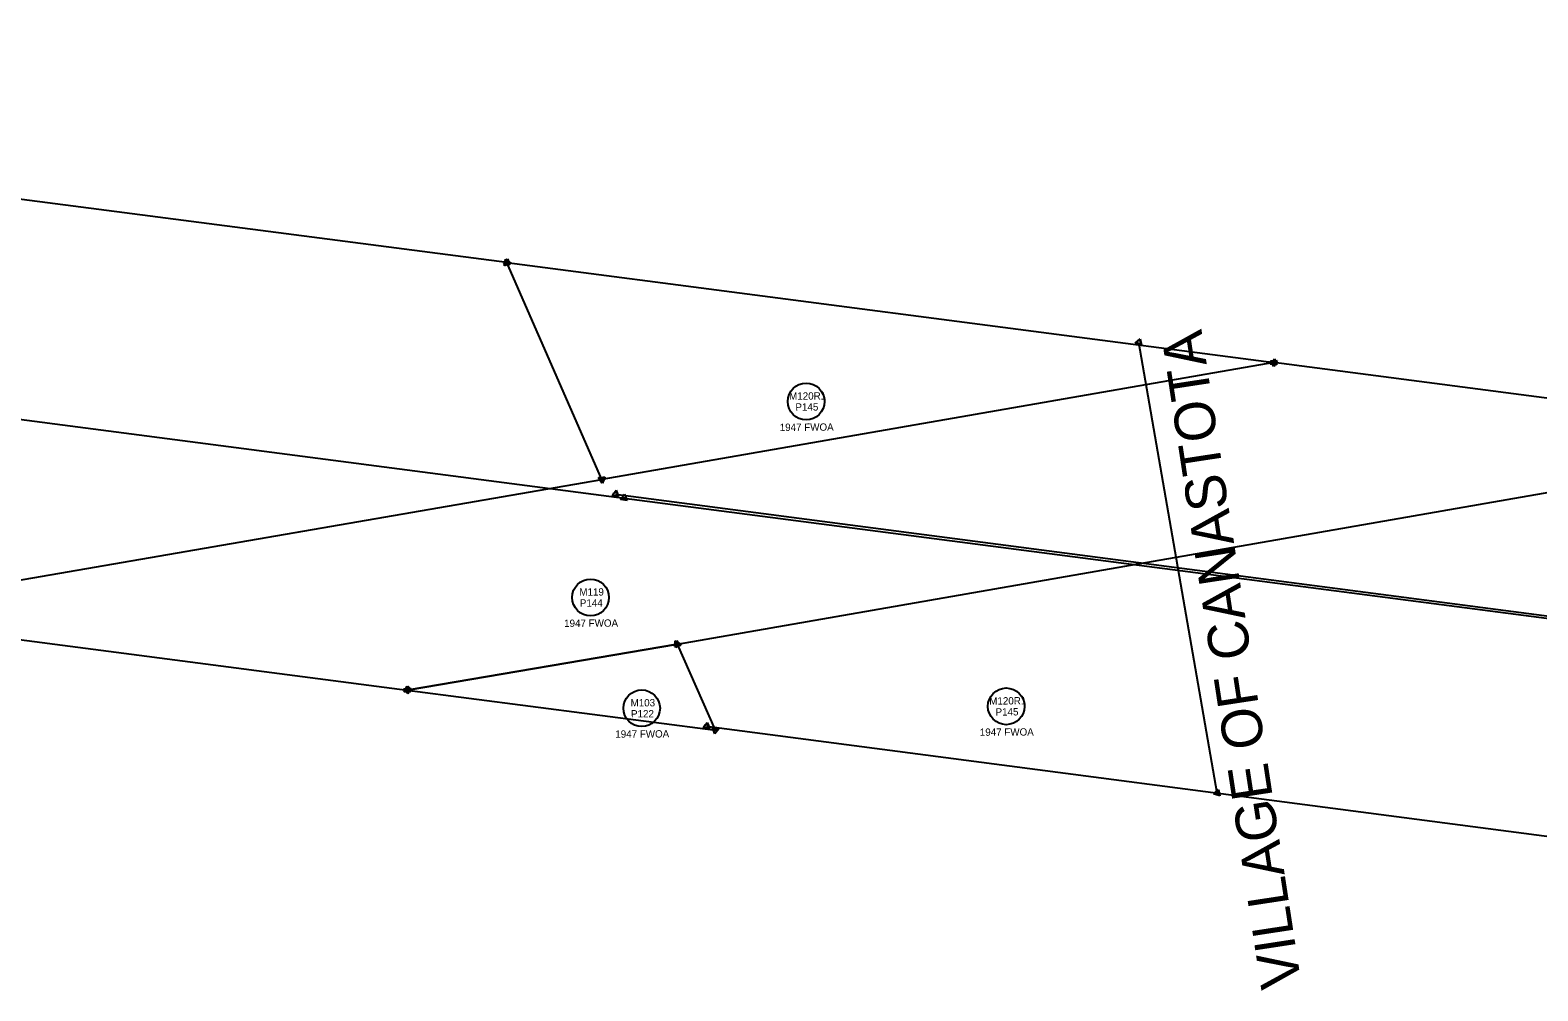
# Model space of a CAD drawing. Extents: x 981880 to 1042422, y 1126107 to 1131189.
# Drawn here: x 1036181 to 1037044, y 1127019 to 1127569 of the extents above; entities that cross this region are included whole.
import ezdxf

# ---------------------------------------------------------------- set-up
doc = ezdxf.new("R2010")
doc.units = 0
for name, color, linetype in [('ADEFAULT', 7, 'Continuous'), ('Level 56', 7, 'Continuous'), ('MHBWOA', 7, 'Continuous'), ('MJV', 7, 'Continuous'), ('MJV_C', 7, 'Continuous'), ('MRBL2', 7, 'Continuous'), ('MRBL3', 7, 'Continuous')]:
    doc.layers.add(name, color=color, linetype=linetype)

msp = doc.modelspace()

# ---------------------------------------------------------------- linework, layer by layer
at = {"layer": 'ADEFAULT'}
for points in [[(1036451.89, 1127435.41), (1036454.19, 1127438.41)], [(1036452.6, 1127434.51), (1036453.05, 1127438.26)], [(1036456.07, 1127435.99), (1036452.6, 1127434.51)], [(1036453.05, 1127438.26), (1036456.07, 1127435.99)], [(1036454.19, 1127438.41), (1036455.64, 1127434.92)], [(1036455.64, 1127434.92), (1036451.89, 1127435.41)], [(1036813.77, 1127390.21), (1036816.67, 1127392.64)], [(1036816.67, 1127392.64), (1036817.32, 1127388.91)], [(1036817.32, 1127388.91), (1036813.77, 1127390.21)], [(1036891.18, 1127378.19), (1036893.48, 1127381.19)], [(1036894.93, 1127377.7), (1036891.18, 1127378.19)], [(1036891.28, 1127380.08), (1036895.06, 1127380.17)], [(1036893.24, 1127376.85), (1036891.28, 1127380.08)], [(1036895.06, 1127380.17), (1036893.24, 1127376.85)], [(1036893.48, 1127381.19), (1036894.93, 1127377.7)], [(1036506.29, 1127312.94), (1036510.01, 1127313.58)], [(1036508.71, 1127310.04), (1036506.29, 1127312.94)], [(1036506.42, 1127313.21), (1036510.19, 1127313.33)], [(1036508.4, 1127310), (1036506.42, 1127313.21)], [(1036510.19, 1127313.33), (1036508.4, 1127310)], [(1036510.01, 1127313.58), (1036508.71, 1127310.04)], [(1036514.1, 1127302.92), (1036516.4, 1127305.92)], [(1036517.85, 1127302.43), (1036514.1, 1127302.92)], [(1036516.4, 1127305.92), (1036517.85, 1127302.43)], [(1036519.04, 1127300.61), (1036521.34, 1127303.61)], [(1036522.79, 1127300.12), (1036519.04, 1127300.61)], [(1036521.34, 1127303.61), (1036522.79, 1127300.12)], [(1036549.83, 1127216.42), (1036551.14, 1127219.96)], [(1036551.14, 1127219.96), (1036553.56, 1127217.06)], [(1036553.56, 1127217.06), (1036549.83, 1127216.42)], [(1036550.48, 1127215.9), (1036550.36, 1127219.67)], [(1036550.36, 1127219.67), (1036553.69, 1127217.88)], [(1036553.69, 1127217.88), (1036550.48, 1127215.9)], [(1036394.78, 1127192.34), (1036398.5, 1127192.97)], [(1036397.19, 1127189.43), (1036394.78, 1127192.34)], [(1036394.81, 1127190.73), (1036397.1, 1127193.73)], [(1036398.56, 1127190.25), (1036394.81, 1127190.73)], [(1036394.96, 1127190.44), (1036396.78, 1127193.75)], [(1036398.73, 1127190.52), (1036394.96, 1127190.44)], [(1036396.78, 1127193.75), (1036398.73, 1127190.52)], [(1036397.1, 1127193.73), (1036398.56, 1127190.25)], [(1036398.5, 1127192.97), (1036397.19, 1127189.43)], [(1036566.3, 1127170.02), (1036568.59, 1127173.02)], [(1036570.04, 1127169.53), (1036566.3, 1127170.02)], [(1036568.59, 1127173.02), (1036570.04, 1127169.53)], [(1036573.08, 1127166.41), (1036571.59, 1127169.89)], [(1036571.59, 1127169.89), (1036575.34, 1127169.44)], [(1036575.34, 1127169.44), (1036573.08, 1127166.41)], [(1036858.67, 1127132.21), (1036861.57, 1127134.63)], [(1036861.57, 1127134.63), (1036862.22, 1127130.9)], [(1036862.22, 1127130.9), (1036858.67, 1127132.21)]]:
    msp.add_lwpolyline(points, dxfattribs=at)
for centre, radius in [((1036453.91, 1127436.25), 1.09), ((1036453.9, 1127436.25), 0.227), ((1036815.92, 1127390.59), 1.09), ((1036893.2, 1127379.03), 1.09), ((1036893.19, 1127379.03), 0.227), ((1036508.33, 1127312.18), 1.09), ((1036508.34, 1127312.18), 0.227), ((1036516.12, 1127303.76), 1.09), ((1036521.06, 1127301.45), 0.227), ((1036551.51, 1127217.81), 0.227), ((1036551.51, 1127217.81), 0.227), ((1036396.82, 1127191.57), 1.09), ((1036396.83, 1127191.57), 1.09), ((1036396.82, 1127191.57), 0.227), ((1036568.31, 1127170.86), 1.09), ((1036573.33, 1127168.58), 0.227), ((1036860.82, 1127132.58), 1.09)]:
    msp.add_circle(centre, radius, dxfattribs=at)
at = {"layer": 'Level 56'}
for centre in [(1036625.28, 1127356.76), (1036501.8, 1127244.56), (1036531.1, 1127181.13), (1036739.92, 1127182.23)]:
    msp.add_circle(centre, 10.5, dxfattribs=at)
at = {"layer": 'MHBWOA'}
for p, q in [((1036453.9, 1127436.25), (1035958.09, 1127500.83)), ((1036508.34, 1127312.18), (1036453.9, 1127436.25)), ((1036453.9, 1127436.25), (1036893.19, 1127379.03)), ((1036893.19, 1127379.03), (1036508.34, 1127312.18)), ((1037227.37, 1127335.5), (1036893.19, 1127379.03)), ((1036551.51, 1127217.81), (1037227.37, 1127335.5)), ((1036062.65, 1127235.1), (1036508.34, 1127312.18)), ((1036062.65, 1127235.1), (1036396.82, 1127191.57)), ((1036551.51, 1127217.81), (1036396.82, 1127191.57)), ((1036396.82, 1127191.57), (1036551.51, 1127217.81)), ((1036573.33, 1127168.58), (1036551.51, 1127217.81)), ((1036396.82, 1127191.57), (1036573.33, 1127168.58)), ((1036568.31, 1127170.86), (1037522.18, 1127046.02))]:
    msp.add_line(p, q, dxfattribs=at)
at = {"layer": 'MJV'}
msp.add_line((1036860.82, 1127132.58), (1036815.92, 1127390.59), dxfattribs=at)
at = {"layer": 'MRBL2'}
for p, q in [((1034464.43, 1127569.33), (1036521.06, 1127301.45)), ((1036521.06, 1127301.45), (1038190.95, 1127083.94))]:
    msp.add_line(p, q, dxfattribs=at)
at = {"layer": 'MRBL3'}
msp.add_line((1036516.12, 1127303.76), (1038185.88, 1127085.22), dxfattribs=at)

# ---------------------------------------------------------------- texts
at = {"layer": 'Level 56'}
for s, p in [('M120R1', (1036615.55, 1127357.76)), ('P145', (1036619.17, 1127351.48)), ('1947 FWOA', (1036610.16, 1127339.87)), ('M119', (1036495.41, 1127245.57)), ('P144', (1036495.69, 1127239.28)), ('1947 FWOA', (1036486.68, 1127227.67)), ('M103', (1036524.74, 1127182.14)), ('M120R1', (1036730.19, 1127183.23)), ('P122', (1036524.99, 1127175.85)), ('P145', (1036733.81, 1127176.95)), ('1947 FWOA', (1036515.98, 1127164.24)), ('1947 FWOA', (1036724.79, 1127165.34))]:
    msp.add_text(s, height=4.199, rotation=0.30243, dxfattribs=at).set_placement(p)
at = {"layer": 'MJV_C'}
msp.add_text('VILLAGE OF CANASTOTA', height=23.2528, rotation=98.69087, dxfattribs=at).set_placement((1036909.1, 1127022.74))

doc.saveas('drawing.dxf')
